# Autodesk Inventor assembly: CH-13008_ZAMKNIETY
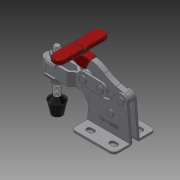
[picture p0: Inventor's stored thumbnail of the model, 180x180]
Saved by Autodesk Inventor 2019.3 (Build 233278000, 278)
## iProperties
Company: Î¢ÈíÖÐ¹ú
Created: 2012-09
Part Number: CH-13008_ZAMKNIETY
Material: Ogólny
Description: STEP AP203
Document SubType Name: Assembly
Designer: CADENGINEERING4
Stock Number: DOCISK PIONOWY
Sending System: SolidWorks 2010
Preprocessor: SwSTEP 2.0
Title: CH-13008.STEP
Author: Î¢ÈíÓÃ»§
Revision Number: ÈÎºÎ
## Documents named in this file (10)
- D:\Vault_2016\Projekty\Clamptek\STRONA\Vertical toggle clamp\CH-13008\CH-13008_ZAMKNIETY.iam
- D:\Vault_2016\Projekty\Clamptek\STRONA\Vertical toggle clamp\CH-13008\CH-13008-05.ipt
- D:\Vault_2016\Projekty\Clamptek\STRONA\Vertical toggle clamp\CH-13008\CH-13008-03 T-HANDLE.ipt
- D:\Vault_2016\Projekty\Clamptek\STRONA\Vertical toggle clamp\CH-13008\CH-13008-02 U-BAR.ipt
- D:\Vault_2016\Projekty\Clamptek\STRONA\Vertical toggle clamp\CH-13008\CH-13008-06.ipt
- D:\Vault_2016\Projekty\Clamptek\STRONA\Vertical toggle clamp\CH-13008\CH-13008-01 FLANGED BASE.ipt
- D:\Vault_2016\Projekty\Clamptek\STRONA\Vertical toggle clamp\CH-13008\CH-FC-38312 Nut.ipt
- D:\Vault_2016\Projekty\Clamptek\STRONA\Vertical toggle clamp\CH-13008\CH-13008-04 CONNECTING-PIATE.ipt
- D:\Vault_2016\Projekty\Clamptek\STRONA\Vertical toggle clamp\CH-13008\CH-FC-38312 SPINDLE SUPPLIED.ipt
- D:\Vault_2016\Projekty\Clamptek\STRONA\Vertical toggle clamp\CH-13008\CH-FW-380.ipt
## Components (18 placed, 18 different names)
1. CH-13008-05_1 — Zestawiające:2
2. CH-13008-03 T-HANDLE_2 — Zestawiające:5, Zestawiające:6, Zestawiające:7, Zestawiające:16, Zestawiające:20
3. CH-13008-02 U-BAR_3 — Zestawiające:22, Zestawiające:24, Zestawiające:25, Zestawiające:26, Zestawiające:27, Zestawiające:35, Kątowe:1, Kątowe:2, Zestawiające:38
4. CH-13008-05_4 — Zestawiające:3, Zestawiające:17, Zestawiające:19
5. CH-13008-06_5 — Zestawiające:12, Zestawiające:15
6. CH-13008-01 FLANGED BASE_6 — Zestawiające:1, Zestawiające:2, Zestawiające:5, Zestawiające:12, Zestawiające:13, Zestawiające:14, Zestawiające:15, Zestawiające:24, Zestawiające:37
7. CH-FC-38312 Nut_7 — Zestawiające:30, Zestawiające:31, Zestawiające:36
8. CH-13008-04 CONNECTING-PIATE_8 — Zestawiające:6, Zestawiające:8, Zestawiające:9, Zestawiające:10, Zestawiające:11, Zestawiające:18, Zestawiające:20
9. CH-13008-06_9 — Zestawiające:9, Zestawiające:10
10. CH-13008-04 CONNECTING-PIATE_10 — Zestawiające:3, Zestawiające:4, Zestawiające:7, Zestawiające:17, Zestawiające:18, Zestawiające:19, Zestawiające:21, Zestawiające:23, Zestawiające:35, Zestawiające:37
11. CH-FC-38312 SPINDLE SUPPLIED_11 — Zestawiające:36, Równoległe:1
12. CH-13008-05_12 — Zestawiające:1
13. CH-FC-38312 Nut_13 — Zestawiające:32, Zestawiające:33
14. CH-FW-380_14 — Zestawiające:25, Zestawiające:28, Zestawiające:32, Zestawiające:33, Równoległe:1, Kątowe:2
15. CH-13008-05_15 — Zestawiające:4, Zestawiające:21
16. CH-13008-06_16 — Zestawiające:8, Zestawiające:11, Zestawiające:22, Zestawiające:23
17. CH-13008-06_17 — Zestawiające:13, Zestawiające:14, Zestawiające:16
18. CH-FW-380_18 — Zestawiające:26, Zestawiające:27, Zestawiające:28, Zestawiające:30, Zestawiające:31, Kątowe:1, Zestawiające:38
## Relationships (39: Mate 36, Angle 2, Flush 1)
- Zestawiające:1 [Mate]: CH-13008-01 FLANGED BASE_6 ↔ CH-13008-05_12
- Zestawiające:2 [Mate]: CH-13008-05_1 ↔ CH-13008-01 FLANGED BASE_6
- Zestawiające:3 [Mate]: CH-13008-05_4 ↔ CH-13008-04 CONNECTING-PIATE_10
- Zestawiające:4 [Mate]: CH-13008-04 CONNECTING-PIATE_10 ↔ CH-13008-05_15
- Zestawiające:5 [Mate]: CH-13008-03 T-HANDLE_2 ↔ CH-13008-01 FLANGED BASE_6
- Zestawiające:6 [Mate]: CH-13008-03 T-HANDLE_2 ↔ CH-13008-04 CONNECTING-PIATE_8
- Zestawiające:7 [Mate]: CH-13008-03 T-HANDLE_2 ↔ CH-13008-04 CONNECTING-PIATE_10
- Zestawiające:8 [Mate]: CH-13008-04 CONNECTING-PIATE_8 ↔ CH-13008-06_16
- Zestawiające:9 [Mate]: CH-13008-04 CONNECTING-PIATE_8 ↔ CH-13008-06_9
- Zestawiające:10 [Mate]: CH-13008-04 CONNECTING-PIATE_8 ↔ CH-13008-06_9
- Zestawiające:11 [Mate]: CH-13008-04 CONNECTING-PIATE_8 ↔ CH-13008-06_16
- Zestawiające:12 [Mate]: CH-13008-06_5 ↔ CH-13008-01 FLANGED BASE_6
- Zestawiające:13 [Mate]: CH-13008-01 FLANGED BASE_6 ↔ CH-13008-06_17
- Zestawiające:14 [Mate]: CH-13008-01 FLANGED BASE_6 ↔ CH-13008-06_17
- Zestawiające:15 [Mate]: CH-13008-06_5 ↔ CH-13008-01 FLANGED BASE_6
- Zestawiające:16 [Mate]: CH-13008-03 T-HANDLE_2 ↔ CH-13008-06_17
- Zestawiające:17 [Mate]: CH-13008-05_4 ↔ CH-13008-04 CONNECTING-PIATE_10
- Zestawiające:18 [Mate]: CH-13008-04 CONNECTING-PIATE_8 ↔ CH-13008-04 CONNECTING-PIATE_10
- Zestawiające:19 [Mate]: CH-13008-05_4 ↔ CH-13008-04 CONNECTING-PIATE_10
- Zestawiające:20 [Mate]: CH-13008-03 T-HANDLE_2 ↔ CH-13008-04 CONNECTING-PIATE_8
- Zestawiające:21 [Mate]: CH-13008-04 CONNECTING-PIATE_10 ↔ CH-13008-05_15
- Zestawiające:22 [Mate]: CH-13008-02 U-BAR_3 ↔ CH-13008-06_16
- Zestawiające:23 [Mate]: CH-13008-04 CONNECTING-PIATE_10 ↔ CH-13008-06_16
- Zestawiające:24 [Mate]: CH-13008-02 U-BAR_3 ↔ CH-13008-01 FLANGED BASE_6
- Zestawiające:25 [Mate]: CH-13008-02 U-BAR_3 ↔ CH-FW-380_14
- Zestawiające:26 [Mate]: CH-13008-02 U-BAR_3 ↔ CH-FW-380_18
- Zestawiające:27 [Mate]: CH-13008-02 U-BAR_3 ↔ CH-FW-380_18
- Zestawiające:28 [Mate]: CH-FW-380_14 ↔ CH-FW-380_18
- Zestawiające:30 [Mate]: CH-FC-38312 Nut_7 ↔ CH-FW-380_18
- Zestawiające:31 [Mate]: CH-FC-38312 Nut_7 ↔ CH-FW-380_18
- Zestawiające:32 [Mate]: CH-FC-38312 Nut_13 ↔ CH-FW-380_14
- Zestawiające:33 [Mate]: CH-FC-38312 Nut_13 ↔ CH-FW-380_14
- Zestawiające:35 [Mate]: CH-13008-02 U-BAR_3 ↔ CH-13008-04 CONNECTING-PIATE_10
- Zestawiające:36 [Mate]: CH-FC-38312 Nut_7 ↔ CH-FC-38312 SPINDLE SUPPLIED_11
- Równoległe:1 [Flush]: CH-FC-38312 SPINDLE SUPPLIED_11 ↔ CH-FW-380_14
- Zestawiające:37 [Mate]: CH-13008-01 FLANGED BASE_6 ↔ CH-13008-04 CONNECTING-PIATE_10
- Kątowe:1 [Angle]: CH-13008-02 U-BAR_3 ↔ CH-FW-380_18
- Kątowe:2 [Angle]: CH-13008-02 U-BAR_3 ↔ CH-FW-380_14
- Zestawiające:38 [Mate]: CH-13008-02 U-BAR_3 ↔ CH-FW-380_18
